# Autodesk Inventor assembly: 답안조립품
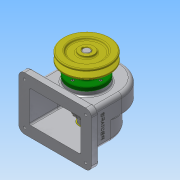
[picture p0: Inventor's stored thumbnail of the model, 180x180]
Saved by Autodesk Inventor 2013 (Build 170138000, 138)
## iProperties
Created: 2017-11
Part Number: 답안조립품
Document SubType Name: Assembly
Designer: Administrator
Author: Administrator
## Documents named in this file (14)
- C:\Users\Administrator\Desktop\471108V1015\답안조립품.iam
- C:\Users\Administrator\Desktop\471108V1015\본체.ipt
- C:\Users\Administrator\Desktop\471108V1015\V-벨트풀리.ipt
- C:\Users\Administrator\Desktop\471108V1015\뒤커버.ipt
- C:\Users\Administrator\Desktop\471108V1015\멈춤나사 - M4 x 10.ipt
- 멈춤나사 - M4 x 10.ipt
- C:\Users\Administrator\Desktop\471108V1015\베어링 6002.ipt
- C:\Users\Administrator\Desktop\471108V1015\볼트 M3 x 8.ipt
- C:\Users\Administrator\Desktop\471108V1015\스퍼기어.ipt
- C:\Users\Administrator\Desktop\471108V1015\앞커버.ipt
- C:\Users\Administrator\Desktop\471108V1015\오일 실 15 30 7.ipt
- C:\Users\Administrator\Desktop\471108V1015\축.ipt
- C:\Users\Administrator\Desktop\471108V1015\키 - 5 x 5 x 18.ipt
- C:\Users\Administrator\Desktop\471108V1015\키 - 6 x 6 x 22.ipt
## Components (1 placed, 1 different names)
1. V-벨트풀리:1
